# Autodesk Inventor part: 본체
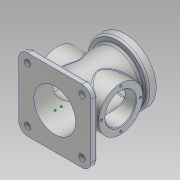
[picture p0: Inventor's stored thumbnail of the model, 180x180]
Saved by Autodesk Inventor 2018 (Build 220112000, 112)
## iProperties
Created: 2021-03
Part Number: 본체
Material: 알루미늄 6061
Document SubType Name: 모델링
Designer: home
Density: 2.7 g/cm^3
Appearance: 알루미늄 - 평지
Mass: 830.882 g
Surface Area: 866.518 cm^2
Volume: 307.734 cm^3
Author: home
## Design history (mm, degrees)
sketch "스케치2"
  geometry: L1 (57, -57)-(-57, -57); L2 (-57, -57)-(-57, 57); L3 (-57, 57)-(57, 57); L4 (57, 57)-(57, -57); 1 further point
  constraints: 8 end point, 2 parallel, 1 horizontal, 1 perpendicular
  dimensions: "d0" = 114 distance of L1.end L2.end; "d1" = 114 distance of L1.start L1.end; "d2" = 57 distance from line of point (0, 0) L2; "d17" = 57 distance from line of point (0, 0) L1
extrude "돌출1" new body sketch "스케치2" distance "d4" = 10; taper "d5" = 0 deg
node "작업 평면1"
sketch "스케치3"
  geometry: L1 (0, 0)-(38, 0); L2 (38, 0)-(38, 98); L3 (0, 63.493)-(0, 0); L4 (38, 98)-(49, 98); L5 (49, 98)-(49, 111); L6 (49, 111)-(0, 111); L7 (0, 111)-(0, 63.493); L8 (57, 0)-(-57, 0) reference
  constraints: 14 end point, 3 parallel, 2 horizontal, 2 perpendicular
  dimensions: "d7" = 49 distance between parallel lines of L7 L5; "d8" = 111 distance between parallel lines of L8 L6; "d9" = 13 distance between parallel lines of L4 L6; "d10" = 38 distance between parallel lines of L3 L2; "d18" = 63.4927 distance from line of L3.start L8
revolve "회전1" sketch "스케치3" stored, may be unused: angle "d11" = 90 deg
sketch "스케치4"
  geometry: L1 (-50, 89)-(50, 89); L2 (50, 89)-(50, 54); L3 (50, 54)-(-50, 54); L4 (-50, 54)-(-50, 89); L5 (57, 0)-(-57, 0) reference; 1 further point
  constraints: 8 end point, 2 parallel, 1 horizontal, 1 perpendicular
  dimensions: "d12" = 54 distance between parallel lines of L5 L3; "d13" = 35 distance between parallel lines of L3 L1; "d14" = 50 distance from line of L2 point (0, 0); "d15" = 100 distance between parallel lines of L4 L2
revolve "회전2" sketch "스케치4" stored, may be unused: angle "d16" = 90 deg
sketch "스케치5"
  geometry: L1 (0, 111)-(37, 111); L2 (37, 111)-(37, 104); L3 (37, 104)-(33, 104); L4 (0, 0)-(0, 165.381); L5 (79.8, 111)-(-79.8, 111) reference; L6 (33, 104)-(33, 0); L7 (33, 0)-(0, 0); L8 (0, 0)-(0, 104); L9 (-57, 0)-(57, 0) reference
  constraints: 14 end point, 2 parallel, 2 point on line, 1 horizontal, 1 perpendicular, 1 vertical
  dimensions: "d19" = 37 distance between parallel lines of L4 L2; "d20" = 0 distance between parallel lines of L5 L1; "d21" = 7 distance between parallel lines of L3 L1; "d22" = 33 distance between parallel lines of L4 L6; "d23" = 0 distance between parallel lines of L7 L9; "d122" = 54.38135 distance from line of L4.end L5; "d123" = 7 distance from line of L8.end L5
revolve "회전3" sketch "스케치5" stored, may be unused: angle "d24" = 90 deg
sketch "스케치6"
  geometry: L1 (-50, 78)-(50, 78); L2 (50, 78)-(50, 54); L3 (50, 54)-(-50, 54); L4 (-50, 54)-(-50, 78); L5 (50, 19)-(50, 89) reference; L6 (-50, 19)-(-50, 89) reference; 1 further point
  constraints: 8 end point, 2 parallel, 1 horizontal, 1 perpendicular
  dimensions: "d25" = 54 distance from line of point (0, 0) L3; "d26" = 24 distance between parallel lines of L3 L1; "d27" = 0 distance between parallel lines of L5 L2; "d28" = 0 distance between parallel lines of L6 L4
revolve "회전4" sketch "스케치6" stored, may be unused: angle "d29" = 90 deg
node "작업 평면2"
sketch "스케치10"
  geometry: C1 r 42 at (0, 0); 2 further points
  constraints: 1 centre point, 1 coincident, 1 horizontal alignment
  dimensions: "d47" = 42 radius of C1; "d121" = 42 distance of point (-42, 0) point (0, 0)
hole "구멍1" sketch "스케치10" at (-42, 0) diameter "d48" = 3.459; stored, may be unused: countersink angle "d52" = 90 deg, drill point angle "d54" = 118 deg; dims "d49" = 6, "d50" = 4, "d51" = 2, "d53" = 8
sketch "스케치11"
  geometry: C1 r 24 at (0, 0) reference; C2 r 35 at (0, 0) reference; C3 r 31 at (0, 0); 2 further points
  constraints: 1 centre point, 1 coincident
  dimensions: "d59" = 62 diameter of C3; "d119" = 31 distance of C1.centre point (31, 0); "d120" = 62.26556 distance of point (0, -54) point (31, 0)
hole "구멍2" sketch "스케치11" at (31, 0) diameter "d60" = 3.459; stored, may be unused: countersink angle "d64" = 90 deg, drill point angle "d66" = 118 deg; dims "d61" = 6, "d62" = 4, "d63" = 2, "d65" = 8
sketch "스케치12"
  geometry: 1 further point
fillet "모깎기3" dims "d70" = 14
sketch "스케치13"
  geometry: L1 (-43, -57)-(43, -57) reference; L2 (57, -43)-(57, 43) reference; L3 (43, 57)-(-43, 57) reference; L4 (-57, 43)-(-57, -43) reference; C1 r 38 at (0, 0) reference; C2 r 5 at (-43, 43); C3 r 5 at (43, 43); C4 r 5 at (43, -43); C5 r 5 at (-43, -43); A1 r 14 centre (-43, -43) between (-57, -43) and (-43, -57) reference; A2 r 14 centre (43, -43) between (43, -57) and (57, -43) reference; A3 r 14 centre (43, 43) between (57, 43) and (43, 57) reference; A4 r 14 centre (-43, 43) between (-43, 57) and (-57, 43) reference; A5 r 14 centre (-43, -43) between (-57, -43) and (-43, -57) reference; 1 further point
  constraints: 4 centre point, 4 coincident, 1 end point
  dimensions: "d71" = 5 radius of C2; "d72" = 5 radius of C3; "d73" = 5 radius of C4; "d74" = 5 radius of C5
extrude "돌출3" cut sketch "스케치13" stored distance "d75" = 23; taper "d76" = 0 deg
fillet "모깎기4" dims "d77" = 3
node "작업 평면3"
sketch "스케치18"
  geometry: L1 (0, 41)-(0, 67); L2 (7, 41)-(7, 70); L3 (-7, 70)-(-7, 41); L4 (-43, 0)-(43, 0) reference; A1 r 7 centre (0, 41) between (-7, 41) and (7, 41); A2 r 7 centre (0, 70) between (7, 70) and (-7, 70); 2 further points
  constraints: 8 end point, 4 point on circle, 4 tangent, 2 centre point, 2 parallel, 1 midpoint, 1 vertical
  dimensions: "d91" = 14 distance between parallel lines of L3 L2; "d92" = 54 distance from line of L4 point (0, 54); "d97" = 36 distance from line of L4.end L2; "d98" = 70 distance from line of L2.end L4; "d99" = 41 distance from line of L2.start L4
extrude "돌출5" join sketch "스케치18" stored distance "d100" = 14; taper "d101" = 15 deg
sketch "스케치19"
  geometry: L1 (-7, 41)-(-7, 70) reference; L2 (7, 70)-(7, 41) reference; A1 r 7 centre (0, 41) between (-7, 41) and (7, 41) reference; A2 r 7 centre (0, 70) between (7, 70) and (-7, 70) reference; 3 further points
  constraints: 2 coincident
  node "투영된 루프5"
sketch "스케치20"
  geometry: 1 further point
hole "구멍3" sketch "스케치19" diameter "d102" = 4.459; stored, may be unused: countersink angle "d106" = 90 deg, drill point angle "d108" = 118 deg; dims "d103" = 8, "d104" = 4, "d105" = 2, "d107" = 10
chamfer "모따기1" distance "d109" = 1; stored, may be unused: second distance "d110" = 2, angle "d111" = 45 deg
fillet "모깎기6" dims "d112" = 3
sketch "스케치21" dims "d113" = 50
  geometry: L1 (0, 0)-(0, 50); 1 further point
  constraints: 2 end point, 1 coincident, 1 vertical, 1 vertical alignment, 2 other
feature "엠보싱1" sketch "스케치21" dims "d0" = 114, "d1" = 114, "d2" = 57, "d17" = 57, "d114" = 0.5, "d115" = 0
chamfer "모따기2" distance "d116" = 1; stored, may be unused: second distance "d117" = 2, angle "d118" = 45 deg
node "솔리드1"
pattern_circular "원형 패턴1" dims angle "d56" = 360 deg
pattern_circular "원형 패턴2" dims angle "d68" = 360 deg
mirror "미러1"
node "투영된 루프2"
node "투영된 루프3"
other parameters: "d6" = -111, "K계수" = 4.4, "BendRadius" = 0.5 (derived), "BendReliefWidth" = 0.5 (derived), "BendReliefDepth" = 0.25 (derived), "CornerReliefSize" = 2 (derived), "SeamGap" = 0.01, "MinimumRemnant" = 1 (derived), "TransitionRadius" = 0.5 (= BendRadius), "d30" = -54, "d90" = -55
